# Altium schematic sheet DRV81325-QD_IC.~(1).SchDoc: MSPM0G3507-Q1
size 431 x 279 mm; Date: Not shown in title block; ApprovedBy: Not shown in title block; CheckedBy: Not shown in title block; Author: Not shown in title block; CompanyName: Not shown in title block; DrawnBy: Mojtaba Afshar; Engineer: Not shown in title block; Organization: Not shown in title block; Address1: Not shown in title block; Address2: Not shown in title block; Address3: Not shown in title block; Address4: Not shown in title block; DocumentNumber: 1; Revision: Use project parameter SCH_Rev; SheetNumber: 2; SheetTotal: 5; PageSetup: Record=PageOptions¦CenterHorizontal=True¦CenterVertical=True¦PrintScale=1.00¦XCorrection=1.00¦YCorrection=1.00¦PrintKind=0¦BorderSize=5000000¦LeftOffset=0¦BottomOffset=0¦Orientation=2¦PaperLength=1000¦PaperWidth=1000¦Scale=100¦PaperSource=15¦PrintQuality=600¦MediaType=1¦DitherType=10¦PaperKind=Letter¦PrintScaleMode=1
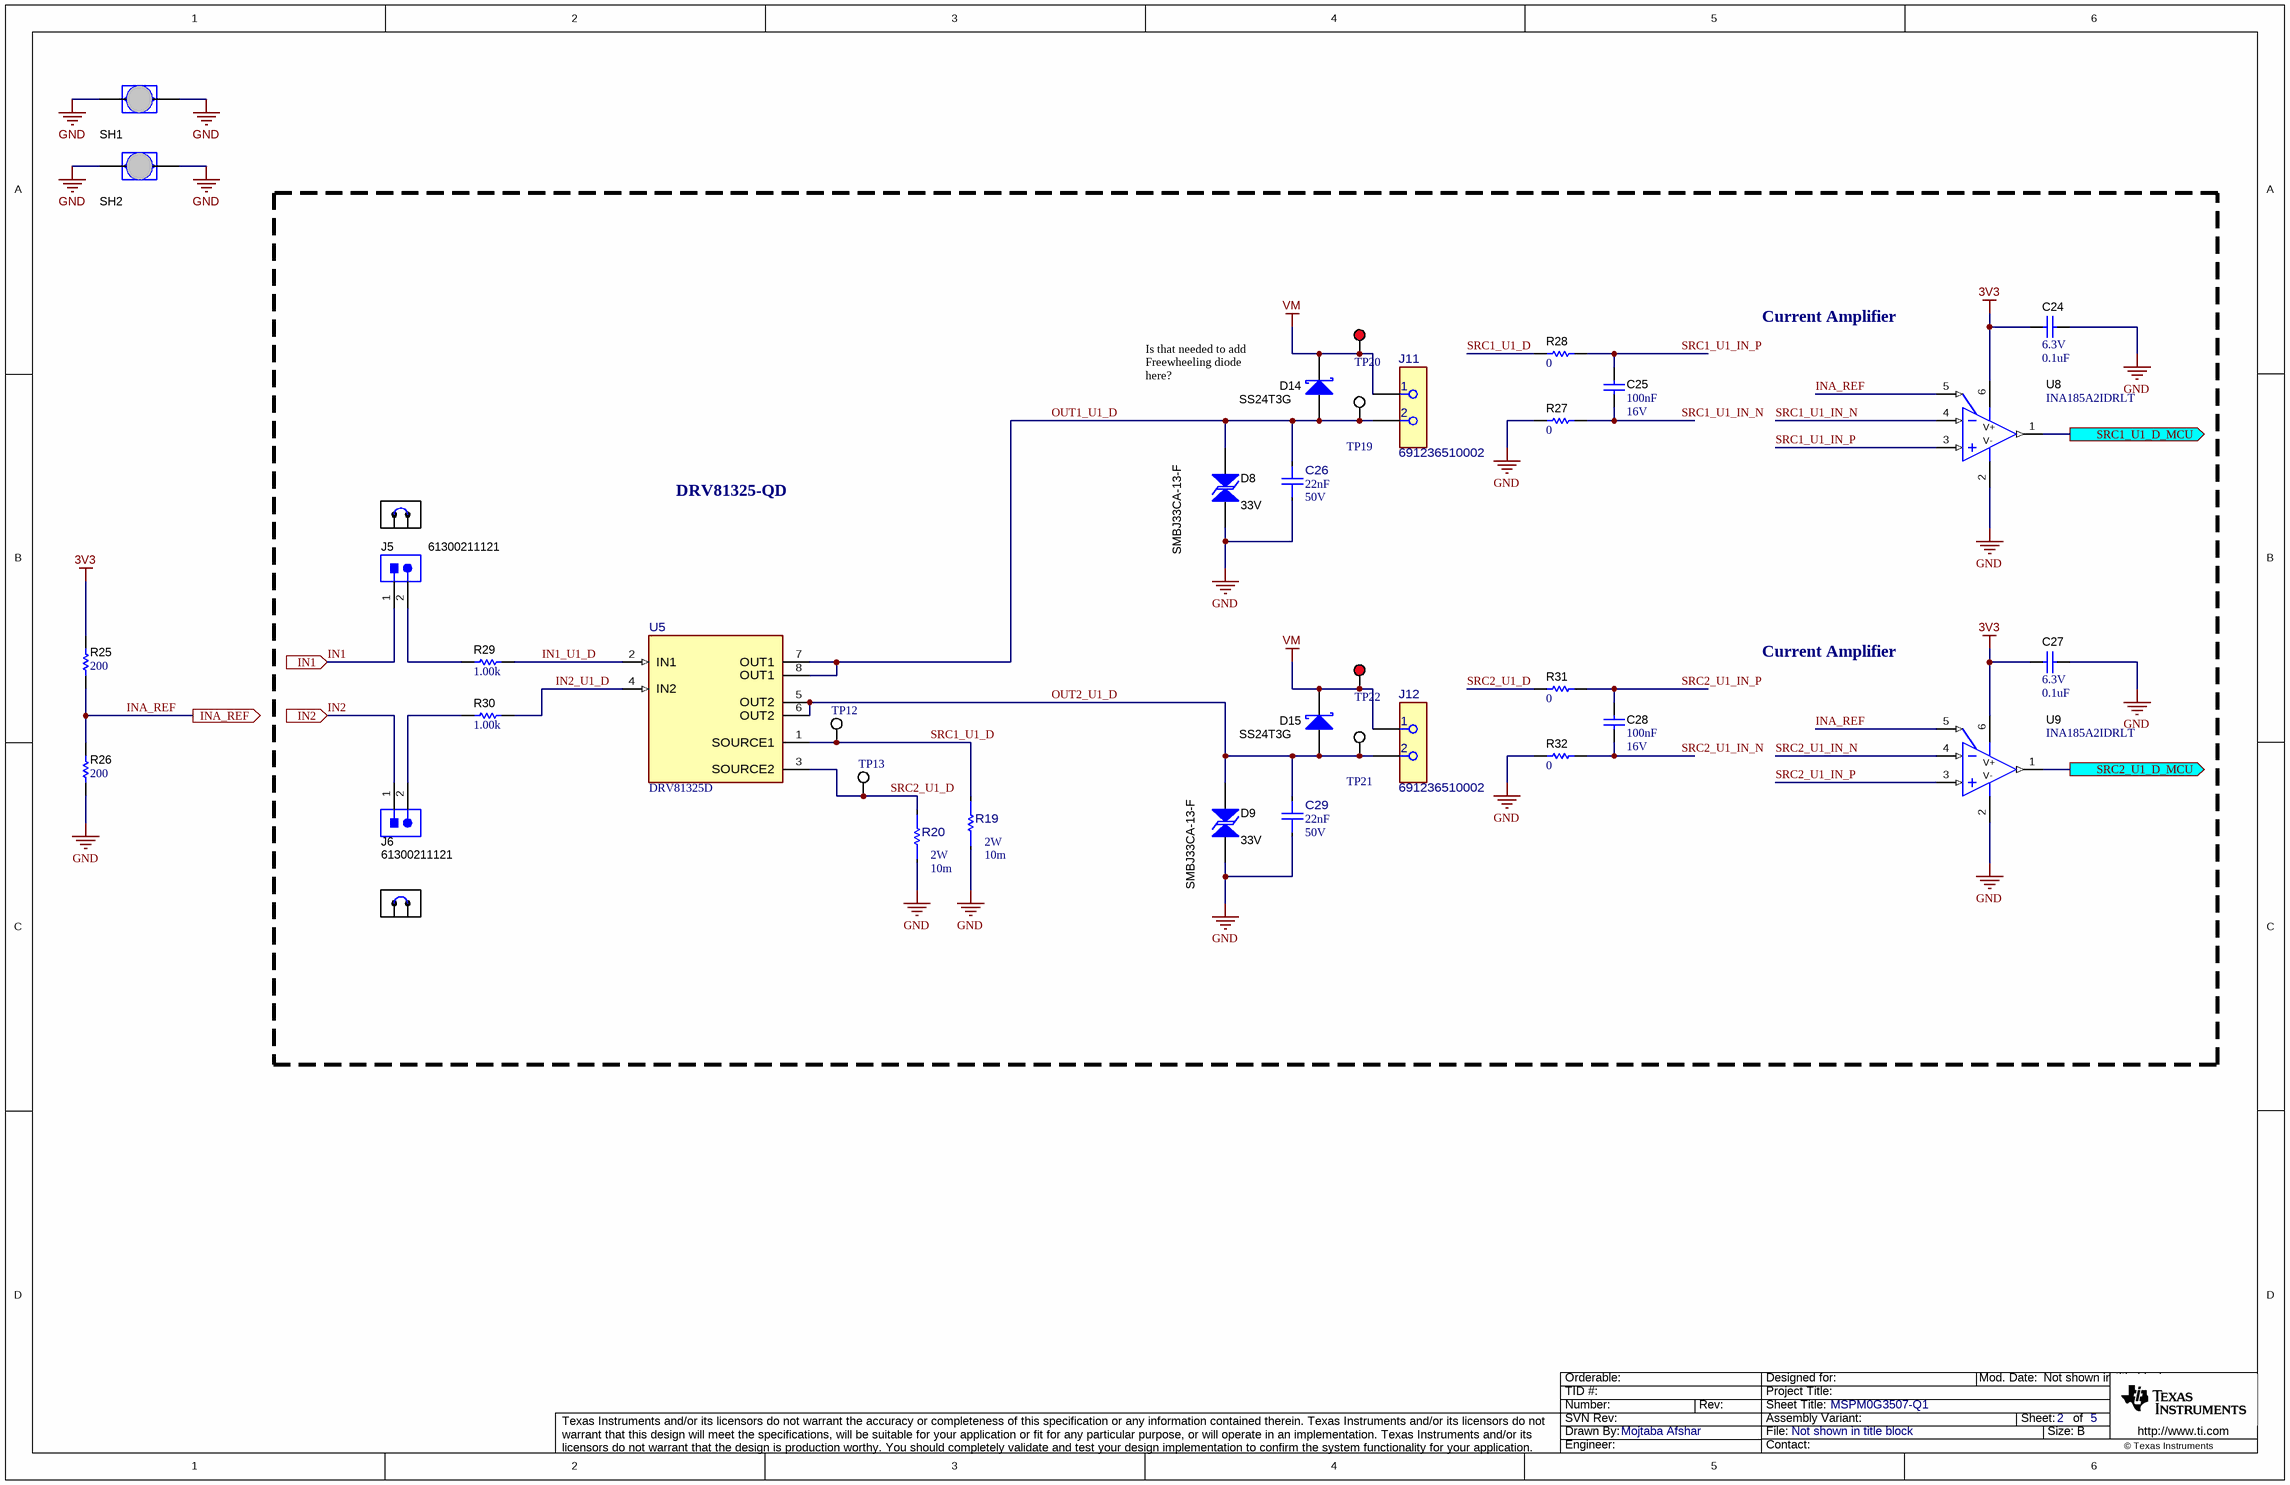
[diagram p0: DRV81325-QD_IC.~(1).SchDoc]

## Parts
C24  VDC_V: 6.3V  ValueDisplayed: 0.1uF  [0402]  (hidden comment: 885012105001)
C25  Cap_F: 100nF  VDC_V: 16V  [0603]  (hidden comment: 885012206046)
C26  Cap_F: 22nF  VDC_V: 50V  [FP-885012206091_0603-MFG]  (hidden comment: 885012206091)
C27  VDC_V: 6.3V  ValueDisplayed: 0.1uF  [0402]  (hidden comment: 885012105001)
C28  Cap_F: 100nF  VDC_V: 16V  [0603]  (hidden comment: 885012206046)
C29  Cap_F: 22nF  VDC_V: 50V  [FP-885012206091_0603-MFG]  (hidden comment: 885012206091)
D8  SMBJ33CA-13-F  value 33V  [SMB-Bi]
D9  SMBJ33CA-13-F  value 33V  [SMB-Bi]
D14  SS24T3G  [SMB]
D15  SS24T3G  [SMB]
J5  61300211121  [WURTH_61300211121]
J6  61300211121  [WURTH_61300211121]
J11  691236510002  [FP-691236510002_HHR2-MFG]
J12  691236510002  [FP-691236510002_HHR2-MFG]
R19  Res_ohm: 10m  Power_W: 2W  [FP-PCS2512DR0100ET_2512-MFG]  (hidden comment: PCS2512DR0100ET)
R20  Res_ohm: 10m  Power_W: 2W  [FP-PCS2512DR0100ET_2512-MFG]  (hidden comment: PCS2512DR0100ET)
R25  ValueDisplayed: 200  [0603]  (hidden comment: RC0603FR-07200RL)
R26  ValueDisplayed: 200  [0603]  (hidden comment: RC0603FR-07200RL)
R27  ValueDisplayed: 0  [0603]  (hidden comment: ERJ-3GEY0R00V)
R28  ValueDisplayed: 0  [0603]  (hidden comment: ERJ-3GEY0R00V)
R29  ValueDisplayed: 1.00k  [0603]  (hidden comment: RC0603FR-071KL)
R30  ValueDisplayed: 1.00k  [0603]  (hidden comment: RC0603FR-071KL)
R31  ValueDisplayed: 0  [0603]  (hidden comment: ERJ-3GEY0R00V)
R32  ValueDisplayed: 0  [0603]  (hidden comment: ERJ-3GEY0R00V)
SH1  Jumper_2p  [Harwin_D3082-05]  (value not drawn)
SH2  Jumper_2p  [Harwin_D3082-05]  (value not drawn)
SH-J5  60900213421  [Wurth_60900213421]  (value not drawn)
SH-J6  60900213421  [Wurth_60900213421]  (value not drawn)
TP12  5002  [Keystone5002]  (value not drawn)
TP13  5002  [Keystone5002]  (value not drawn)
TP19  5012  [Keystone5012]  (value not drawn)
TP20  5010  [Keystone5010]  (value not drawn)
TP21  5012  [Keystone5012]  (value not drawn)
TP22  5010  [Keystone5010]  (value not drawn)
U5  DRV81325D  [D0008A-MFG]
U8  INA185A2IDRLT  [DRL0006A]
U9  INA185A2IDRLT  [DRL0006A]

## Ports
IN1 (in), IN2 (in), INA_REF (out), SRC1_U1_D_MCU (out), SRC2_U1_D_MCU (out)

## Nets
3V3: C24.2 C27.2 R25.2 U8.6(V+) U9.6(V+)
GND: C24.1 C26.1 C27.1 C29.1 D8.1 D9.1 R19.1 R20.1 R26.1 R27.1 R32.1 SH1.1 SH1.2 SH2.1 SH2.2 U8.2(V-) U9.2(V-)
VM: D14.1(K) D15.1(K) J11.1 J12.1 TP20.1 TP22.1
IN1: J5.1 ; port IN1
IN1_U1_D: R29.2 U5.2(IN1)
IN2: J6.1 ; port IN2
IN2_U1_D: R30.2 U5.4(IN2)
INA_REF: R25.1 R26.2 U8.5(REF) U9.5(REF) ; port INA_REF
OUT1_U1_D: C26.2 D8.2 D14.2(A) J11.2 TP19.1 U5.7(OUT1) U5.8(OUT1)
OUT2_U1_D: C29.2 D9.2 D15.2(A) J12.2 TP21.1 U5.5(OUT2) U5.6(OUT2)
SRC1_U1_D: R19.2 R28.1 TP12.1 U5.1(SOURCE1)
SRC1_U1_D_MCU: U8.1(OUT) ; port SRC1_U1_D_MCU
SRC1_U1_IN_N: C25.2 R27.2 U8.4(IN-)
SRC1_U1_IN_P: C25.1 R28.2 U8.3(IN+)
SRC2_U1_D: R20.2 R31.1 TP13.1 U5.3(SOURCE2)
SRC2_U1_D_MCU: U9.1(OUT) ; port SRC2_U1_D_MCU
SRC2_U1_IN_N: C28.2 R32.2 U9.4(IN-)
SRC2_U1_IN_P: C28.1 R31.2 U9.3(IN+)
NetJ5_2: J5.2 R29.1
NetJ6_2: J6.2 R30.1

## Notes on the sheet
- Current Amplifier
- Is that needed to add Freewheeling diode here?
- DRV81325-QD

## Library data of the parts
C24 C27 = CMP-0006219-2: CAP, CERM, 0.1 uF, 6.3 V, +/- 20%, X5R, 0402; Manufacturer: Wurth Elektronik; TaMin_C: -55°C; Polarized: N; SizeAreaWB_mm2: 3; Value1: Unknown; U/M: EA; Value: 0.1uF; TaMax_C: 85°C; SizeZ_mm: 0.6; SizeX_mm: 1; SizeY_mm: 0.5; Cap_F: 100nF; AEC Category: Q200
C25 C28 = CMP-0006829-4: CAP, CERM, 0.1 uF, 16 V, +/- 10%, X7R, 0603; Manufacturer: Wurth Elektronik; TaMin_C: -55°C; Polarized: N; SizeAreaWB_mm2: 4.68; Value1: Unknown; U/M: EA; Value: 0.1uF; TaMax_C: 125°C; SizeZ_mm: 1; SizeX_mm: 1.6; SizeY_mm: 0.8; SizeArea_mm2: 1.28; AEC Category: Q200
C26 C29 = CMP-0120895-1: 0.022 µF ±10% 50V Ceramic Capacitor X7R 0603 (1608 Metric); Manufacturer: Wurth Electronics; AEC Qualified: No; SizeZ_mm: 0.87mm; TempCo: 15%; Value: 22nF
D8 D9 = CMP-0005564-3: Diode, TVS, Bi, 33 V, SMB; Manufacturer: Diodes Inc.; SizeX_mm: 5.6; Ppk: 600W; SizeAreaWB_mm2: 44.156; SizeZ_mm: 2.6; SizeArea_mm2: 21.336; SizeY_mm: 3.81; AEC Category: Q101
D14 D15 = CMP-0028778-2: Diode, Schottky, 40 V, 2 A, AEC-Q101, SMB; Manufacturer: ON Semiconductor; AEC Qualified: Y; Value: 40V; TJmax_C: 150°C; Value1: 2A; Green_Lifecycle: Active; Value2: 0.5V; SizeX_mm: 5.6; SizeAreaWB_mm2: 44.156; SizeY_mm: 3.81; SizeArea_mm2: 21.336; Green_REACh: Passed; SizeZ_mm: 2.6; AEC Category: Q101; Vf_V: 500mV
J5 J6 = CMP-0054794-2: Header, 2.54 mm, 2x1, Gold, TH; Manufacturer: Wurth Elektronik; Shrouded: N; Gender: Male; Green_REACh: Passed; Pitch_mm: 2.54; Green_Lifecycle: Active; Row_Count: 1; Cert_UL: Y
J11 J12 = CMP-0121282-1: 2 Position Wire to Board Terminal Block Horizontal with Board 0.200" (5.08mm) Through Hole; Manufacturer: Wurth Electronics; Current_A: 20A; Row_Count: 1; Voltage_V: 300V; AEC Qualified: No; Conn Gender: Female; Is Female: yes; Max Wire Gauge: 12; Min Wire Gauge: 30; SizeZ_mm: 18.1mm
R19 R20 = CMP-0088493-1: 10 mOhms ±0.5% 2W Chip Resistor 2512 (6432 Metric) Automotive AEC-Q200, Current Sense, Moisture Resistant Metal Film; Manufacturer: Ohmite; SizeZ_mm: 0.664mm; AEC Grade: Grade 0; TempCo: 50ppm/°C; AEC Qualified: Yes; Tolerance_%: 0%
R25 R26 = CMP-0022902-5: RES, 200, 1%, 0.1 W, 0603; Manufacturer: Yageo; Power_W: 100mW; TempCo: 100 ppm/C; Value_Code: 200R; Value: 200; EIA_Code: E96; SizeX_mm: 1.6; SizeY_mm: 0.8; SizeZ_mm: 1; Value2: 0.1W; SizeArea_mm2: 1.28; AEC Qualified: N; VDC_V: 75V; AEC Category: Q200; SizeAreaWB_mm2: 4.68
R27 R28 R31 R32 = CMP-0025874-4: RES, 0, 5%, 0.1 W, AEC-Q200 Grade 0, 0603; Manufacturer: Panasonic; Power_W: 100mW; TempCo: 600 ppm/C; Value_Code: 0000; Value: 0; EIA_Code: E24; SizeX_mm: 1.6; SizeY_mm: 0.8; SizeZ_mm: 1; Value2: 0.1W; SizeArea_mm2: 1.28; AEC Qualified: Y; VDC_V: 50V; AEC Category: Q200; SizeAreaWB_mm2: 4.68
R29 R30 = CMP-0022895-5: RES, 1.00 k, 1%, 0.1 W, 0603; Manufacturer: Yageo; Power_W: 100mW; TempCo: 100 ppm/C; Value_Code: 1k00; Value: 1.00k; EIA_Code: E96; Res_ohm: 1k; SizeX_mm: 1.6; SizeY_mm: 0.8; SizeZ_mm: 1; Value2: 0.1W; SizeArea_mm2: 1.28; AEC Qualified: N; VDC_V: 75V; AEC Category: Q200; SizeAreaWB_mm2: 4.68
SH1 SH2 = CMP-0075110-1: 1mm Uninsulated Shorting Plug, 10.16mm spacing, TH; PartNumber: D3082-05; Manufacturer: Harwin; CNHeader: False; CompType: Jumper Wire; Green_Lifecycle: Active; Green_REACh: Passed
SH-J5 SH-J6 = CMP-0003761-2: Shunt, 2.54mm, Gold, Black; Manufacturer: Wurth Elektronik
TP12 TP13 = CMP-0055139-2: Test Point, Miniature, White, TH; Manufacturer: Keystone Electronics; ContactFinish: Silver; Green_REACh: Passed; CT: TRUE; Green_Lifecycle: Active; CNHeader: FALSE
TP19 TP21 = CMP-0055149-2: Test Point, Multipurpose, White, TH; Manufacturer: Keystone Electronics; ContactFinish: Silver; CT: TRUE; CNHeader: FALSE; Green_Lifecycle: Active; Green_REACh: Passed
TP20 TP22 = CMP-0055147-2: Test Point, Multipurpose, Red, TH; Manufacturer: Keystone Electronics; CT: TRUE; ContactFinish: Silver; Green_Lifecycle: Active; CNHeader: FALSE; Green_REACh: Passed
U5 = CMP-0127644-1: Dual Channel Protected Low side switch, SOIC8; Manufacturer: Texas Instruments; SizeZ_mm: 1.75mm; AEC Qualified: Yes; AEC Grade: Grade 1; Max Supply Voltage: 5.5V; Min Supply Voltage: 3V; Number Of Outputs: 2; Standoff Height: 0.11mm; TaMax_C: +125°C; TaMin_C: -40°C; TJmax_C: +150°C
U8 U9 = CMP-0085241-1: Bidirectional, Precision Low- and High-Side Voltage Output, Current-Sense Amplifier, DRL0006A (SOT-5X3-6); Alternate Manufacturer: Texas Instruments; Alternate PartNumber: INA185A2IDRLR; SizeZ_mm: 0.6; CompType: IC; SizeY_mm: 1.6; SizeAreaWB_mm2: 6.76; AEC Qualified: N; SizeArea_mm2: 2.56; AEC Category: Q200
